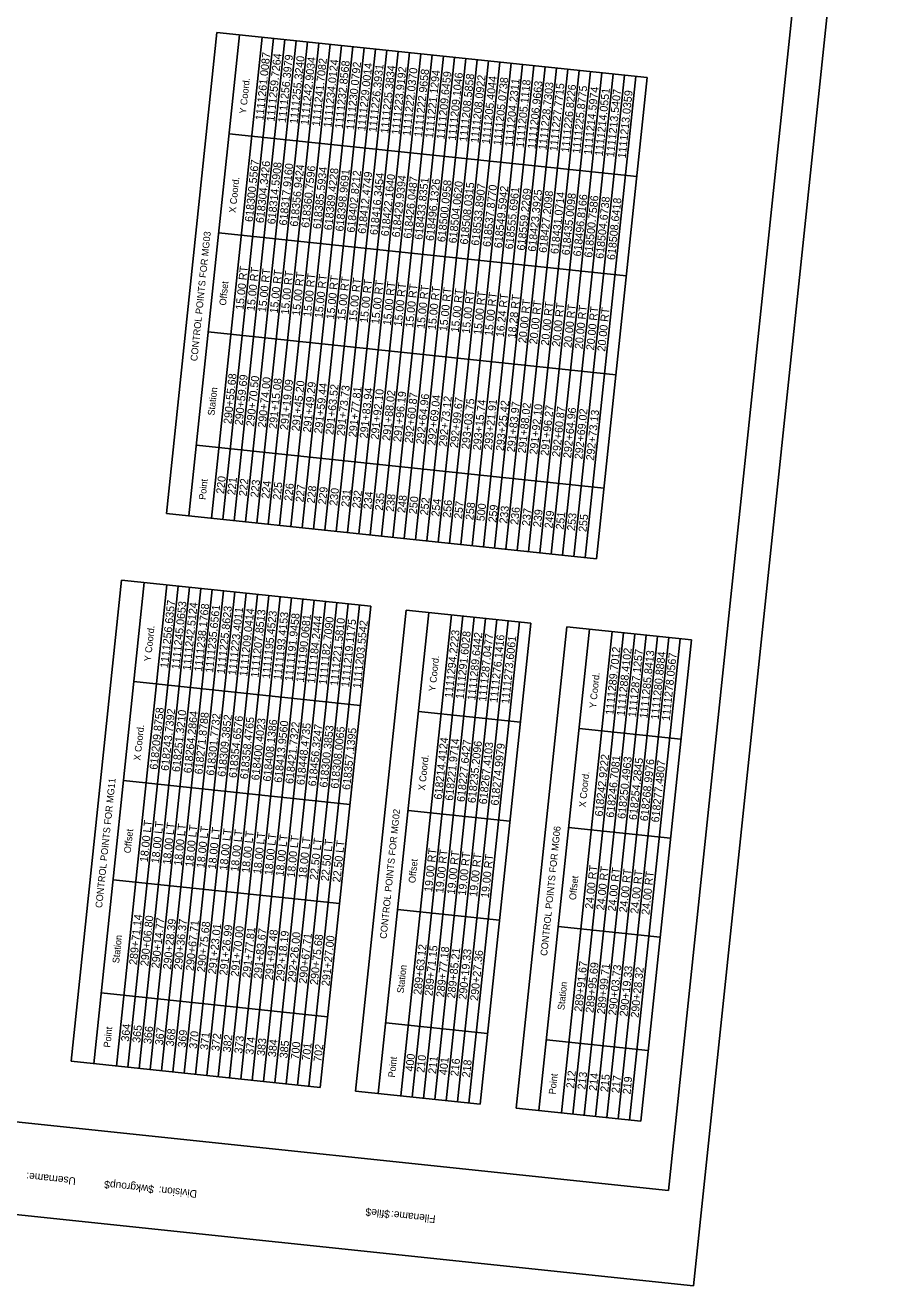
# Model space of a CAD drawing. Extents: x 1111051 to 1111686, y 618367 to 619270.
# Drawn here: x 1111304 to 1111686, y 618367 to 618921 of the extents above; entities that cross this region are included whole.
import ezdxf

# ---------------------------------------------------------------- set-up
doc = ezdxf.new("R2010")
doc.units = 0
for name, color, linetype in [('ANNOTATION', 7, 'Continuous'), ('BORDER', 7, 'Continuous'), ('H_V CONTROLS', 7, 'Continuous'), ('PLOT BOUNDARY', 7, 'Continuous')]:
    doc.layers.add(name, color=color, linetype=linetype)

msp = doc.modelspace()

# ---------------------------------------------------------------- linework, layer by layer
at = {"layer": 'BORDER'}
for p, q in [((1111586.64, 618409.2), (1111670.26, 619204.81)), ((1111064.52, 618464.07), (1111586.64, 618409.2))]:
    msp.add_line(p, q, dxfattribs=at)
at = {"layer": 'H_V CONTROLS'}
for p, q in [((1111366.07, 618706.49), (1111388.29, 618917.83)), ((1111388.29, 618917.83), (1111577.25, 618897.97)), ((1111376.02, 618705.45), (1111398.23, 618916.78)), ((1111385.97, 618704.4), (1111408.18, 618915.74)), ((1111390.94, 618703.88), (1111413.15, 618915.21)), ((1111395.91, 618703.36), (1111418.12, 618914.69)), ((1111400.88, 618702.83), (1111423.1, 618914.17)), ((1111405.86, 618702.31), (1111428.07, 618913.65)), ((1111410.83, 618701.79), (1111433.04, 618913.12)), ((1111415.8, 618701.26), (1111438.01, 618912.6)), ((1111420.77, 618700.74), (1111442.99, 618912.08)), ((1111425.75, 618700.22), (1111447.96, 618911.56)), ((1111430.72, 618699.7), (1111452.93, 618911.03)), ((1111435.69, 618699.17), (1111457.9, 618910.51)), ((1111440.66, 618698.65), (1111462.88, 618909.99)), ((1111445.64, 618698.13), (1111467.85, 618909.46)), ((1111450.61, 618697.61), (1111472.82, 618908.94)), ((1111455.58, 618697.08), (1111477.79, 618908.42)), ((1111460.55, 618696.56), (1111482.77, 618907.9)), ((1111465.53, 618696.04), (1111487.74, 618907.37)), ((1111470.5, 618695.52), (1111492.71, 618906.85)), ((1111475.47, 618694.99), (1111497.68, 618906.33)), ((1111480.44, 618694.47), (1111502.66, 618905.81)), ((1111485.42, 618693.95), (1111507.63, 618905.28)), ((1111490.39, 618693.43), (1111512.6, 618904.76)), ((1111495.36, 618692.9), (1111517.57, 618904.24)), ((1111500.34, 618692.38), (1111522.55, 618903.72)), ((1111505.31, 618691.86), (1111527.52, 618903.19)), ((1111510.28, 618691.33), (1111532.49, 618902.67)), ((1111515.25, 618690.81), (1111537.47, 618902.15)), ((1111520.23, 618690.29), (1111542.44, 618901.63)), ((1111525.2, 618689.77), (1111547.41, 618901.1)), ((1111530.17, 618689.24), (1111552.38, 618900.58)), ((1111535.14, 618688.72), (1111557.36, 618900.06)), ((1111540.12, 618688.2), (1111562.33, 618899.53)), ((1111545.09, 618687.68), (1111567.3, 618899.01)), ((1111550.06, 618687.15), (1111572.27, 618898.49)), ((1111555.03, 618686.63), (1111577.25, 618897.97)), ((1111555.03, 618686.63), (1111577.25, 618897.97)), ((1111393.66, 618873.27), (1111572.67, 618854.46)), ((1111389.09, 618829.76), (1111568.1, 618810.95)), ((1111384.51, 618786.25), (1111563.53, 618767.44)), ((1111379.29, 618736.52), (1111558.3, 618717.71)), ((1111366.07, 618706.49), (1111555.03, 618686.63)), ((1111324.23, 618465.94), (1111346.44, 618677.27)), ((1111334.18, 618464.89), (1111356.39, 618676.23)), ((1111344.12, 618463.85), (1111366.33, 618675.18)), ((1111346.44, 618677.27), (1111455.84, 618665.78)), ((1111349.1, 618463.32), (1111371.31, 618674.66)), ((1111354.07, 618462.8), (1111376.28, 618674.14)), ((1111359.04, 618462.28), (1111381.25, 618673.61)), ((1111364.01, 618461.76), (1111386.23, 618673.09)), ((1111368.99, 618461.23), (1111391.2, 618672.57)), ((1111373.96, 618460.71), (1111396.17, 618672.05)), ((1111378.93, 618460.19), (1111401.14, 618671.52)), ((1111383.9, 618459.67), (1111406.12, 618671)), ((1111388.88, 618459.14), (1111411.09, 618670.48)), ((1111393.85, 618458.62), (1111416.06, 618669.96)), ((1111398.82, 618458.1), (1111421.03, 618669.43)), ((1111403.79, 618457.57), (1111426.01, 618668.91)), ((1111408.77, 618457.05), (1111430.98, 618668.39)), ((1111413.74, 618456.53), (1111435.95, 618667.87)), ((1111418.71, 618456.01), (1111440.92, 618667.34)), ((1111423.68, 618455.48), (1111445.9, 618666.82)), ((1111428.66, 618454.96), (1111450.87, 618666.3)), ((1111433.63, 618454.44), (1111455.84, 618665.78)), ((1111433.63, 618454.44), (1111455.84, 618665.78)), ((1111449.22, 618452.8), (1111471.44, 618664.14)), ((1111459.17, 618451.75), (1111481.38, 618663.09)), ((1111471.44, 618664.14), (1111526.13, 618658.39)), ((1111469.11, 618450.71), (1111491.33, 618662.05)), ((1111474.09, 618450.19), (1111496.3, 618661.52)), ((1111479.06, 618449.66), (1111501.27, 618661)), ((1111484.03, 618449.14), (1111506.24, 618660.48)), ((1111489, 618448.62), (1111511.22, 618659.95)), ((1111493.98, 618448.1), (1111516.19, 618659.43)), ((1111498.95, 618447.57), (1111521.16, 618658.91)), ((1111503.92, 618447.05), (1111526.13, 618658.39)), ((1111503.92, 618447.05), (1111526.13, 618658.39)), ((1111519.77, 618445.39), (1111541.98, 618656.72)), ((1111541.98, 618656.72), (1111596.68, 618650.97)), ((1111529.71, 618444.34), (1111551.93, 618655.68)), ((1111539.66, 618443.3), (1111561.87, 618654.63)), ((1111544.63, 618442.77), (1111566.84, 618654.11)), ((1111549.6, 618442.25), (1111571.82, 618653.59)), ((1111554.58, 618441.73), (1111576.79, 618653.06)), ((1111559.55, 618441.2), (1111581.76, 618652.54)), ((1111564.52, 618440.68), (1111586.73, 618652.02)), ((1111569.49, 618440.16), (1111591.71, 618651.5)), ((1111574.47, 618439.64), (1111596.68, 618650.97)), ((1111574.47, 618439.64), (1111596.68, 618650.97)), ((1111351.82, 618632.72), (1111451.27, 618622.26)), ((1111476.81, 618619.58), (1111521.56, 618614.88)), ((1111547.35, 618612.17), (1111592.11, 618607.46)), ((1111347.24, 618589.21), (1111446.7, 618578.75)), ((1111472.23, 618576.07), (1111516.99, 618571.37)), ((1111542.78, 618568.66), (1111587.53, 618563.95)), ((1111342.67, 618545.7), (1111442.12, 618535.24)), ((1111467.66, 618532.56), (1111512.41, 618527.86)), ((1111538.21, 618525.15), (1111582.96, 618520.44)), ((1111337.44, 618495.97), (1111436.9, 618485.52)), ((1111462.43, 618482.83), (1111507.19, 618478.13)), ((1111532.98, 618475.42), (1111577.73, 618470.72)), ((1111324.23, 618465.94), (1111433.63, 618454.44)), ((1111449.22, 618452.8), (1111503.92, 618447.05)), ((1111519.77, 618445.39), (1111574.47, 618439.64))]:
    msp.add_line(p, q, dxfattribs=at)
at = {"layer": 'PLOT BOUNDARY'}
msp.add_lwpolyline([(1111597.62, 618367.35), (1111686.47, 619212.69), (1111139.49, 619270.18), (1111050.64, 618424.84)], close=True, dxfattribs=at)

# ---------------------------------------------------------------- texts
at = {"layer": 'ANNOTATION'}
for s, height, p in [('1111261.0087', 3.5156, (1111408.65, 618879.02)), ('1111259.7264', 3.5156, (1111413.54, 618878.51)), ('1111256.3979', 3.5156, (1111418.58, 618877.98)), ('1111255.3240', 3.5156, (1111423.69, 618877.44)), ('1111242.9034', 3.5156, (1111428.51, 618876.94)), ('1111241.7082', 3.5156, (1111433.47, 618876.41)), ('1111234.0124', 3.5156, (1111438.54, 618875.88)), ('1111232.8568', 3.5156, (1111443.51, 618875.36)), ('1111230.0792', 3.5156, (1111448.47, 618874.84)), ('1111229.0014', 3.5156, (1111453.43, 618874.32)), ('1111226.3931', 3.5156, (1111458.36, 618873.8)), ('1111225.3834', 3.5156, (1111463.54, 618873.25)), ('1111223.9192', 3.5133, (1111468.43, 618872.74)), ('1111222.0370', 3.5133, (1111473.28, 618872.23)), ('1111222.9658', 3.5133, (1111478.36, 618871.7)), ('1111221.1294', 3.5133, (1111483.19, 618871.19)), ('1111209.6459', 3.5133, (1111488.2, 618870.66)), ('1111209.1046', 3.5133, (1111493.23, 618870.13)), ('1111208.5858', 3.5156, (1111498.2, 618869.61)), ('1111208.0922', 3.5156, (1111503.16, 618869.09)), ('1111205.4044', 3.5156, (1111508.11, 618868.57)), ('1111205.0738', 3.5156, (1111513.14, 618868.04)), ('1111204.2311', 3.5156, (1111518.13, 618867.52)), ('1111205.1118', 3.5156, (1111522.98, 618867.01)), ('1111206.9663', 3.5156, (1111528.2, 618866.46)), ('1111228.7303', 3.5133, (1111533.01, 618865.95)), ('1111227.7715', 3.5133, (1111537.83, 618865.45)), ('1111226.8226', 3.5133, (1111542.94, 618864.91)), ('1111225.8775', 3.5133, (1111547.83, 618864.4)), ('1111214.5974', 3.5133, (1111552.87, 618863.86)), ('1111214.0551', 3.5133, (1111557.77, 618863.35)), ('1111213.5407', 3.5156, (1111562.73, 618862.83)), ('1111213.0359', 3.5156, (1111567.8, 618862.3)), ('618300.5567', 3.5156, (1111403.97, 618834.44)), ('618304.3426', 3.5156, (1111408.86, 618833.92)), ('618314.5908', 3.5156, (1111413.89, 618833.39)), ('618317.9160', 3.5156, (1111419, 618832.86)), ('618356.9424', 3.5156, (1111423.82, 618832.35)), ('618360.7596', 3.5156, (1111428.78, 618831.83)), ('618385.5934', 3.5156, (1111433.86, 618831.3)), ('618389.4228', 3.5156, (1111438.82, 618830.77)), ('618398.9691', 3.5156, (1111443.78, 618830.25)), ('618402.8212', 3.5156, (1111448.75, 618829.73)), ('618412.4749', 3.5156, (1111453.67, 618829.21)), ('618416.3454', 3.5156, (1111458.85, 618828.67)), ('618422.1640', 3.5133, (1111463.74, 618828.15)), ('618429.9394', 3.5133, (1111468.6, 618827.64)), ('618426.0487', 3.5133, (1111473.67, 618827.11)), ('618433.8351', 3.5133, (1111478.51, 618826.6)), ('618496.1326', 3.5133, (1111483.51, 618826.08)), ('618500.0958', 3.5133, (1111488.55, 618825.55)), ('618504.0620', 3.5156, (1111493.51, 618825.03)), ('618508.0315', 3.5156, (1111498.48, 618824.5)), ('618533.8907', 3.5156, (1111503.42, 618823.98)), ('618537.8770', 3.5156, (1111508.46, 618823.45)), ('618549.5942', 3.5156, (1111513.44, 618822.93)), ('618555.6961', 3.5156, (1111518.29, 618822.42)), ('618559.2269', 3.5156, (1111523.51, 618821.87)), ('618423.3925', 3.5133, (1111528.32, 618821.37)), ('618427.2098', 3.5133, (1111533.14, 618820.86)), ('618431.0714', 3.5133, (1111538.25, 618820.32)), ('618435.0098', 3.5133, (1111543.14, 618819.81)), ('618496.8166', 3.5133, (1111548.19, 618819.28)), ('618500.7586', 3.5133, (1111553.08, 618818.76)), ('618504.6738', 3.5156, (1111558.04, 618818.24)), ('618508.6418', 3.5156, (1111563.12, 618817.71)), ('15.00 RT', 3.516, (1111399.91, 618795.81)), ('15.00 RT', 3.516, (1111404.8, 618795.3)), ('15.00 RT', 3.516, (1111409.83, 618794.77)), ('15.00 RT', 3.516, (1111414.94, 618794.23)), ('15.00 RT', 3.516, (1111419.76, 618793.72)), ('15.00 RT', 3.516, (1111424.72, 618793.2)), ('15.00 RT', 3.516, (1111429.62, 618792.69)), ('15.00 RT', 3.516, (1111434.65, 618792.16)), ('15.00 RT', 3.516, (1111439.76, 618791.62)), ('15.00 RT', 3.516, (1111444.58, 618791.12)), ('15.00 RT', 3.516, (1111449.61, 618790.59)), ('15.00 RT', 3.516, (1111454.51, 618790.07)), ('15.00 RT', 3.516, (1111459.54, 618789.54)), ('15.00 RT', 3.516, (1111464.65, 618789.01)), ('15.00 RT', 3.516, (1111469.47, 618788.5)), ('15.00 RT', 3.516, (1111474.45, 618787.98)), ('15.00 RT', 3.516, (1111479.45, 618787.45)), ('15.00 RT', 3.516, (1111484.35, 618786.94)), ('15.00 RT', 3.516, (1111489.38, 618786.41)), ('15.00 RT', 3.516, (1111494.49, 618785.87)), ('15.00 RT', 3.516, (1111499.31, 618785.36)), ('15.00 RT', 3.516, (1111504.4, 618784.83)), ('15.00 RT', 3.516, (1111509.29, 618784.31)), ('16.24 RT', 3.516, (1111514.24, 618783.79)), ('18.28 RT', 3.516, (1111519.45, 618783.25)), ('20.00 RT', 3.516, (1111524.1, 618781.19)), ('20.00 RT', 3.516, (1111528.92, 618780.68)), ('20.00 RT', 3.516, (1111534.03, 618780.15)), ('20.00 RT', 3.516, (1111538.92, 618779.63)), ('20.00 RT', 3.513, (1111543.96, 618779.1)), ('20.00 RT', 3.513, (1111548.86, 618778.59)), ('20.00 RT', 3.516, (1111553.89, 618778.06)), ('20.00 RT', 3.516, (1111558.79, 618777.54)), ('290+55.68', 3.516, (1111394.63, 618745.64)), ('290+59.69', 3.516, (1111399.53, 618745.13)), ('290+70.50', 3.516, (1111404.56, 618744.6)), ('290+74.00', 3.516, (1111409.67, 618744.06)), ('291+15.08', 3.516, (1111414.49, 618743.56)), ('291+19.09', 3.516, (1111419.45, 618743.03)), ('291+45.20', 3.516, (1111424.52, 618742.5)), ('291+49.29', 3.516, (1111429.49, 618741.98)), ('291+59.44', 3.516, (1111434.45, 618741.46)), ('291+63.52', 3.516, (1111439.41, 618740.94)), ('291+73.73', 3.516, (1111444.34, 618740.42)), ('291+77.81', 3.516, (1111449.52, 618739.87)), ('291+83.94', 3.513, (1111454.41, 618739.36)), ('291+92.10', 3.513, (1111459.26, 618738.85)), ('291+88.02', 3.513, (1111464.34, 618738.32)), ('291+96.19', 3.513, (1111469.17, 618737.81)), ('292+60.87', 3.513, (1111474.18, 618737.28)), ('292+64.96', 3.513, (1111479.21, 618736.75)), ('292+69.04', 3.516, (1111484.18, 618736.23)), ('292+73.12', 3.516, (1111489.14, 618735.71)), ('292+99.67', 3.516, (1111494.09, 618735.19)), ('293+03.75', 3.516, (1111499.13, 618734.66)), ('293+15.74', 3.516, (1111504.11, 618734.14)), ('293+21.91', 3.516, (1111509.04, 618734.35)), ('293+25.42', 3.516, (1111514.25, 618733.8)), ('291+83.97', 3.513, (1111519.07, 618733.29)), ('291+88.02', 3.513, (1111523.89, 618732.79)), ('291+92.10', 3.513, (1111528.99, 618732.25)), ('291+96.27', 3.513, (1111533.88, 618731.73)), ('292+60.87', 3.513, (1111538.93, 618731.2)), ('292+64.96', 3.513, (1111543.82, 618730.69)), ('292+69.02', 3.516, (1111548.79, 618730.17)), ('292+73.13', 3.516, (1111553.86, 618729.64)), ('220', 3.516, (1111391.41, 618715)), ('221', 3.516, (1111396.3, 618714.48)), ('222', 3.516, (1111401.34, 618713.95)), ('223', 3.516, (1111406.45, 618713.42)), ('224', 3.516, (1111411.27, 618712.91)), ('225', 3.516, (1111416.23, 618712.39)), ('226', 3.516, (1111421.3, 618711.85)), ('227', 3.516, (1111426.27, 618711.33)), ('228', 3.516, (1111431.23, 618710.81)), ('229', 3.516, (1111436.19, 618710.29)), ('230', 3.516, (1111441.12, 618709.77)), ('231', 3.516, (1111446.3, 618709.23)), ('232', 3.516, (1111451.19, 618708.71)), ('234', 3.516, (1111456.05, 618708.2)), ('235', 3.516, (1111461.12, 618707.67)), ('238', 3.516, (1111465.96, 618707.16)), ('248', 3.516, (1111470.96, 618706.63)), ('250', 3.516, (1111476, 618706.11)), ('252', 3.516, (1111480.96, 618705.58)), ('254', 3.516, (1111485.92, 618705.06)), ('256', 3.516, (1111490.87, 618704.54)), ('257', 3.516, (1111495.9, 618704.01)), ('258', 3.516, (1111500.89, 618703.49)), ('500', 3.516, (1111505.74, 618702.98)), ('259', 3.516, (1111510.96, 618702.43)), ('233', 3.516, (1111515.77, 618701.93)), ('236', 3.516, (1111520.59, 618701.42)), ('237', 3.516, (1111525.7, 618700.88)), ('239', 3.516, (1111530.59, 618700.37)), ('249', 3.516, (1111535.64, 618699.84)), ('251', 3.516, (1111540.53, 618699.32)), ('253', 3.516, (1111545.49, 618698.8)), ('255', 3.516, (1111550.56, 618698.27)), ('1111256.6357', 3.5156, (1111366.85, 618638.47)), ('1111245.0653', 3.5156, (1111371.81, 618637.94)), ('1111242.5124', 3.5156, (1111376.7, 618637.43)), ('1111238.1768', 3.5156, (1111381.78, 618636.9)), ('1111235.6561', 3.5156, (1111386.58, 618636.39)), ('1111225.8623', 3.5156, (1111391.74, 618635.85)), ('1111223.4011', 3.5156, (1111396.7, 618635.33)), ('1111209.0414', 3.5156, (1111401.59, 618634.81)), ('1111207.8513', 3.5156, (1111406.55, 618634.29)), ('1111195.4523', 3.5133, (1111411.53, 618633.77)), ('1111193.4153', 3.5133, (1111416.61, 618633.24)), ('1111191.9458', 3.5133, (1111421.53, 618632.72)), ('1111190.0681', 3.5133, (1111426.48, 618632.2)), ('1111184.2444', 3.5133, (1111431.38, 618631.68)), ('1111182.7090', 3.5133, (1111436.48, 618631.15)), ('1111221.5810', 3.5133, (1111441.44, 618630.63)), ('1111219.1175', 3.5133, (1111446.33, 618630.11)), ('1111203.5542', 3.5133, (1111451.44, 618629.57)), ('1111294.2223', 3.5156, (1111491.75, 618625.34)), ('1111291.6028', 3.5156, (1111496.64, 618624.82)), ('1111289.6442', 3.5156, (1111501.76, 618624.29)), ('1111287.0477', 3.5156, (1111506.56, 618623.78)), ('1111276.1416', 3.5156, (1111511.53, 618623.26)), ('1111273.6061', 3.5156, (1111516.65, 618622.72)), ('1111289.7012', 3.5156, (1111562.38, 618617.91)), ('1111288.4102', 3.5156, (1111567.35, 618617.39)), ('1111287.1257', 3.5156, (1111572.35, 618616.87)), ('1111285.8413', 3.5156, (1111577.35, 618616.34)), ('1111280.8884', 3.5156, (1111582.28, 618615.82)), ('1111278.0567', 3.5156, (1111587.16, 618615.31)), ('618209.8758', 3.5156, (1111362.16, 618593.88)), ('618243.7392', 3.5156, (1111367.12, 618593.36)), ('618251.3210', 3.5156, (1111372.01, 618592.84)), ('618264.2864', 3.5156, (1111377.09, 618592.31)), ('618271.8788', 3.5156, (1111381.9, 618591.81)), ('618301.7732', 3.5156, (1111387.05, 618591.26)), ('618309.3852', 3.5156, (1111392.01, 618590.74)), ('618354.6576', 3.5156, (1111396.9, 618590.23)), ('618358.4765', 3.5156, (1111401.87, 618589.71)), ('618400.4023', 3.5133, (1111406.84, 618589.18)), ('618408.1386', 3.5133, (1111411.92, 618588.65)), ('618413.9560', 3.5133, (1111416.84, 618588.13)), ('618421.7322', 3.5133, (1111421.79, 618587.61)), ('618448.4735', 3.5133, (1111426.69, 618587.1)), ('618456.3247', 3.5133, (1111431.8, 618586.56)), ('618300.3853', 3.5133, (1111436.75, 618586.04)), ('618308.0065', 3.5133, (1111441.65, 618585.52)), ('618357.1395', 3.5133, (1111446.75, 618584.99)), ('618214.4124', 3.5156, (1111487.07, 618580.75)), ('618221.9714', 3.5156, (1111491.95, 618580.24)), ('618227.6427', 3.5156, (1111497.07, 618579.7)), ('618235.2096', 3.5156, (1111501.88, 618579.19)), ('618267.4103', 3.5156, (1111506.84, 618578.67)), ('618274.9979', 3.5156, (1111511.96, 618578.13)), ('618242.9222', 3.5156, (1111557.7, 618573.33)), ('618246.7081', 3.5156, (1111562.66, 618572.81)), ('618250.4963', 3.5156, (1111567.66, 618572.28)), ('618254.2845', 3.5156, (1111572.67, 618571.75)), ('618268.9976', 3.5156, (1111577.59, 618571.24)), ('618277.4807', 3.5156, (1111582.47, 618570.72)), ('18.00 LT', 3.516, (1111357.89, 618553.25)), ('18.00 LT', 3.516, (1111362.87, 618552.72)), ('18.00 LT', 3.516, (1111367.92, 618552.19)), ('18.00 LT', 3.516, (1111372.82, 618551.68)), ('18.00 LT', 3.516, (1111377.8, 618551.15)), ('18.00 LT', 3.516, (1111382.78, 618550.63)), ('18.00 LT', 3.516, (1111387.76, 618550.11)), ('18.00 LT', 3.516, (1111392.8, 618549.58)), ('18.00 LT', 3.516, (1111397.71, 618549.06)), ('18.00 LT', 3.513, (1111402.57, 618548.55)), ('18.00 LT', 3.513, (1111407.65, 618548.02)), ('18.00 LT', 3.513, (1111412.57, 618547.5)), ('18.00 LT', 3.513, (1111417.52, 618546.98)), ('18.00 LT', 3.513, (1111422.42, 618546.46)), ('18.00 LT', 3.513, (1111427.53, 618545.93)), ('22.50 LT', 3.513, (1111432.48, 618545.41)), ('22.50 LT', 3.513, (1111437.38, 618544.89)), ('22.50 LT', 3.513, (1111442.48, 618544.36)), ('19.00 RT', 3.516, (1111482.79, 618540.12)), ('19.00 RT', 3.516, (1111487.68, 618539.61)), ('19.00 RT', 3.516, (1111492.8, 618539.07)), ('19.00 RT', 3.516, (1111497.61, 618538.56)), ('19.00 RT', 3.516, (1111502.57, 618538.04)), ('19.00 RT', 3.516, (1111507.69, 618537.5)), ('24.00 RT', 3.516, (1111553.43, 618532.7)), ('24.00 RT', 3.516, (1111558.39, 618532.17)), ('24.00 RT', 3.516, (1111563.39, 618531.65)), ('24.00 RT', 3.516, (1111568.4, 618531.12)), ('24.00 RT', 3.516, (1111573.32, 618530.6)), ('24.00 RT', 3.516, (1111578.2, 618530.09)), ('289+71.14', 3.516, (1111353.15, 618508.11)), ('290+06.80', 3.516, (1111358.11, 618507.58)), ('290+14.77', 3.516, (1111362.95, 618506.66)), ('290+28.39', 3.516, (1111368.03, 618506.13)), ('290+36.37', 3.516, (1111372.88, 618506.03)), ('290+67.71', 3.516, (1111378.03, 618505.49)), ('290+75.68', 3.516, (1111383, 618504.97)), ('291+23.01', 3.516, (1111387.85, 618504.04)), ('291+26.99', 3.516, (1111392.81, 618503.52)), ('291+70.00', 3.513, (1111397.78, 618503)), ('291+77.81', 3.513, (1111402.86, 618502.47)), ('291+83.67', 3.513, (1111407.79, 618501.95)), ('291+91.48', 3.513, (1111412.74, 618501.43)), ('292+18.19', 3.513, (1111417.64, 618500.91)), ('292+26.00', 3.513, (1111422.74, 618500.38)), ('290+67.71', 3.513, (1111427.69, 618499.86)), ('290+75.68', 3.513, (1111432.59, 618499.34)), ('291+27.00', 3.513, (1111437.69, 618498.81)), ('289+63.12', 3.516, (1111478.05, 618494.98)), ('289+71.15', 3.516, (1111482.93, 618494.46)), ('289+77.18', 3.516, (1111488.06, 618493.93)), ('289+85.21', 3.516, (1111492.86, 618493.42)), ('290+19.33', 3.516, (1111497.83, 618492.9)), ('290+27.36', 3.516, (1111502.95, 618492.36)), ('289+91.67', 3.516, (1111548.68, 618487.55)), ('289+95.69', 3.516, (1111553.64, 618487.03)), ('289+99.71', 3.516, (1111558.65, 618486.51)), ('290+03.73', 3.516, (1111563.65, 618485.98)), ('290+19.33', 3.516, (1111568.57, 618485.46)), ('290+28.32', 3.516, (1111573.46, 618484.95)), ('364', 3.516, (1111349.61, 618474.44)), ('365', 3.516, (1111354.57, 618473.92)), ('366', 3.516, (1111359.46, 618473.4)), ('367', 3.516, (1111364.54, 618472.87)), ('368', 3.516, (1111369.34, 618472.36)), ('369', 3.516, (1111374.5, 618471.82)), ('370', 3.516, (1111379.46, 618471.3)), ('371', 3.516, (1111384.35, 618470.79)), ('372', 3.516, (1111389.31, 618470.26)), ('382', 3.513, (1111394.29, 618469.74)), ('373', 3.513, (1111399.37, 618469.21)), ('374', 3.513, (1111404.29, 618468.69)), ('383', 3.513, (1111409.24, 618468.17)), ('384', 3.513, (1111414.14, 618467.66)), ('385', 3.513, (1111419.24, 618467.12)), ('700', 3.513, (1111424.2, 618466.6)), ('701', 3.513, (1111429.09, 618466.08)), ('702', 3.513, (1111434.2, 618465.55)), ('400', 3.516, (1111474.51, 618461.31)), ('210', 3.516, (1111479.4, 618460.8)), ('211', 3.516, (1111484.52, 618460.26)), ('401', 3.516, (1111489.32, 618459.75)), ('216', 3.516, (1111494.29, 618459.23)), ('218', 3.516, (1111499.41, 618458.69)), ('212', 3.516, (1111545.14, 618453.89)), ('213', 3.516, (1111550.11, 618453.36)), ('214', 3.516, (1111555.11, 618452.84)), ('215', 3.516, (1111560.11, 618452.31)), ('217', 3.516, (1111565.04, 618451.8)), ('219', 3.516, (1111569.92, 618451.28))]:
    msp.add_text(s, height=height, rotation=84, dxfattribs=at).set_placement(p)
at = {"layer": 'BORDER'}
for s, p in [('Username:', (1111326.47, 618414.85)), ('$wkgroup$', (1111360.77, 618411.24)), ('Division:', (1111379.68, 618409.25)), ('$file$', (1111464.42, 618400.35)), ('Filename:', (1111484.44, 618398.24))]:
    msp.add_text(s, height=3.348, rotation=174, dxfattribs=at).set_placement(p)
at = {"layer": 'H_V CONTROLS'}
for s, p in [('Y Coord.', (1111401.11, 618881.95)), ('X Coord.', (1111396.53, 618838.44)), ('CONTROL POINTS FOR MG03', (1111379.63, 618773.3)), ('Offset', (1111392.26, 618797.74)), ('Station', (1111387.18, 618749.41)), ('Point', (1111383.29, 618712.41)), ('Y Coord.', (1111359.26, 618641.4)), ('Y Coord.', (1111484.26, 618628.26)), ('Y Coord.', (1111554.8, 618620.85)), ('X Coord.', (1111354.69, 618597.89)), ('X Coord.', (1111479.68, 618584.75)), ('X Coord.', (1111550.23, 618577.34)), ('CONTROL POINTS FOR MG11', (1111337.83, 618533.17)), ('CONTROL POINTS FOR MG02', (1111462.78, 618519.61)), ('CONTROL POINTS FOR MG06', (1111533.32, 618512.11)), ('Offset', (1111350.41, 618557.18)), ('Offset', (1111475.4, 618544.05)), ('Offset', (1111545.95, 618536.63)), ('Station', (1111345.33, 618508.86)), ('Station', (1111470.33, 618495.72)), ('Station', (1111540.87, 618488.31)), ('Point', (1111341.44, 618471.85)), ('Point', (1111466.44, 618458.72)), ('Point', (1111536.98, 618451.3))]:
    msp.add_text(s, height=3, rotation=84, dxfattribs=at).set_placement(p)

doc.saveas('drawing.dxf')
